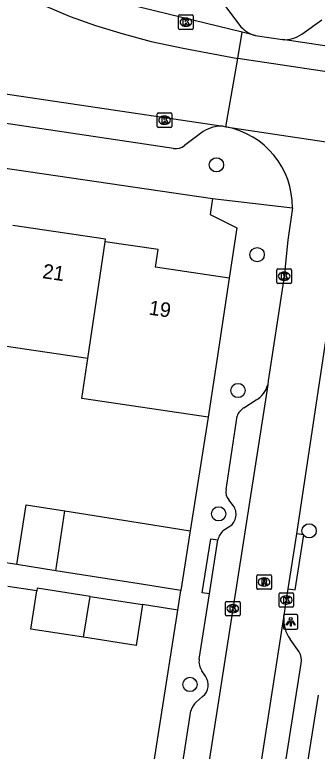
# Model space of a CAD drawing. Extents: x 163010 to 163853, y 382793 to 383982.
# Drawn here: x 163269.9 to 163290.6, y 383210.8 to 383261.3 of the extents above; entities that cross this region are included whole.
import ezdxf

# ---------------------------------------------------------------- set-up
doc = ezdxf.new("R2010")
doc.units = 0
for name, color, linetype in [('IMGEO_Boom', 7, 'Continuous'), ('IMGEO_Kolk', 7, 'Continuous'), ('IMGEO_Lichtpunt', 7, 'Continuous'), ('IMGEO_Muur', 7, 'Continuous'), ('IMGEO_Pand', 7, 'Continuous'), ('IMGEO_Pand_nummerreeks', 7, 'Continuous'), ('IMGEO_Rijbaan_lokaal_gesloten', 7, 'Continuous'), ('IMGEO_Rijbaan_lokaal_open', 7, 'Continuous'), ('IMGEO_Rioolput', 7, 'Continuous'), ('IMGEO_Voetpad_open', 7, 'Continuous')]:
    doc.layers.add(name, color=color, linetype=linetype)

msp = doc.modelspace()

# ---------------------------------------------------------------- linework, layer by layer
at = {"layer": 'IMGEO_Boom'}
for centre in [(163283.714, 383251.013), (163286.5, 383244.851), (163285.192, 383235.53), (163283.866, 383227.066), (163290.064, 383225.904), (163281.894, 383215.363)]:
    msp.add_circle(centre, 0.489, dxfattribs=at)
at = {"layer": 'IMGEO_Kolk'}
for p, q in [((163281.122, 383260.374), (163281.122, 383261.226)), ((163281.197, 383261.3), (163282.049, 383261.3)), ((163281.61, 383261.08), (163281.635, 383261.08)), ((163282.123, 383261.226), (163282.123, 383260.374)), ((163281.633, 383260.52), (163281.608, 383260.52)), ((163282.049, 383260.3), (163281.197, 383260.3)), ((163279.661, 383253.651), (163279.661, 383254.503)), ((163279.736, 383254.577), (163280.588, 383254.577)), ((163280.149, 383254.357), (163280.174, 383254.357)), ((163280.662, 383254.503), (163280.662, 383253.651)), ((163280.588, 383253.577), (163279.736, 383253.577)), ((163280.172, 383253.797), (163280.147, 383253.797)), ((163287.853, 383242.946), (163287.853, 383243.798)), ((163287.928, 383243.872), (163288.78, 383243.872)), ((163288.854, 383243.798), (163288.854, 383242.946)), ((163288.341, 383243.652), (163288.366, 383243.652)), ((163288.78, 383242.872), (163287.928, 383242.872)), ((163288.364, 383243.092), (163288.339, 383243.092)), ((163288, 383220.732), (163288, 383221.584)), ((163288.075, 383221.658), (163288.927, 383221.658)), ((163289.001, 383221.584), (163289.001, 383220.732)), ((163284.333, 383220.138), (163284.333, 383220.99)), ((163284.408, 383221.064), (163285.26, 383221.064)), ((163285.334, 383220.99), (163285.334, 383220.138)), ((163288.488, 383221.438), (163288.513, 383221.438)), ((163284.821, 383220.844), (163284.846, 383220.844)), ((163288.927, 383220.658), (163288.075, 383220.658)), ((163288.511, 383220.878), (163288.486, 383220.878)), ((163285.26, 383220.064), (163284.408, 383220.064)), ((163284.844, 383220.284), (163284.819, 383220.284))]:
    msp.add_line(p, q, dxfattribs=at)
for points in [[(163281.122, 383260.374), (163281.122, 383261.226)], [(163281.197, 383261.3), (163282.049, 383261.3)], [(163281.443, 383261), (163281.566, 383261), (163281.566, 383260.849), (163281.696, 383261), (163281.86, 383261), (163281.714, 383260.849), (163281.867, 383260.6), (163281.715, 383260.6), (163281.63, 383260.764), (163281.566, 383260.697), (163281.566, 383260.6), (163281.443, 383260.6), (163281.443, 383261)], [(163282.123, 383261.226), (163282.123, 383260.374)], [(163282.049, 383260.3), (163281.197, 383260.3)], [(163279.661, 383253.651), (163279.661, 383254.503)], [(163279.736, 383254.577), (163280.588, 383254.577)], [(163280.662, 383254.503), (163280.662, 383253.651)], [(163279.982, 383254.277), (163280.105, 383254.277), (163280.105, 383254.126), (163280.235, 383254.277), (163280.399, 383254.277), (163280.253, 383254.126), (163280.406, 383253.877), (163280.254, 383253.877), (163280.169, 383254.041), (163280.105, 383253.974), (163280.105, 383253.877), (163279.982, 383253.877), (163279.982, 383254.277)], [(163280.588, 383253.577), (163279.736, 383253.577)], [(163287.853, 383242.946), (163287.853, 383243.798)], [(163287.928, 383243.872), (163288.78, 383243.872)], [(163288.854, 383243.798), (163288.854, 383242.946)], [(163288.174, 383243.572), (163288.297, 383243.572), (163288.297, 383243.421), (163288.427, 383243.572), (163288.591, 383243.572), (163288.445, 383243.421), (163288.598, 383243.172), (163288.446, 383243.172), (163288.361, 383243.336), (163288.297, 383243.269), (163288.297, 383243.172), (163288.174, 383243.172), (163288.174, 383243.572)], [(163288.78, 383242.872), (163287.928, 383242.872)], [(163288, 383220.732), (163288, 383221.584)], [(163288.075, 383221.658), (163288.927, 383221.658)], [(163289.001, 383221.584), (163289.001, 383220.732)], [(163284.333, 383220.138), (163284.333, 383220.99)], [(163284.408, 383221.064), (163285.26, 383221.064)], [(163285.334, 383220.99), (163285.334, 383220.138)], [(163288.321, 383221.358), (163288.444, 383221.358), (163288.444, 383221.207), (163288.574, 383221.358), (163288.738, 383221.358), (163288.592, 383221.207), (163288.745, 383220.958), (163288.593, 383220.958), (163288.508, 383221.122), (163288.444, 383221.055), (163288.444, 383220.958), (163288.321, 383220.958), (163288.321, 383221.358)], [(163284.654, 383220.764), (163284.777, 383220.764), (163284.777, 383220.613), (163284.907, 383220.764), (163285.071, 383220.764), (163284.925, 383220.613), (163285.078, 383220.364), (163284.926, 383220.364), (163284.841, 383220.528), (163284.777, 383220.461), (163284.777, 383220.364), (163284.654, 383220.364), (163284.654, 383220.764)], [(163288.927, 383220.658), (163288.075, 383220.658)], [(163285.26, 383220.064), (163284.408, 383220.064)]]:
    msp.add_lwpolyline(points, dxfattribs=at)
for centre, start, end in [((163281.199, 383261.224), 91.552, 178.448), ((163281.199, 383261.224), 91.552, 178.448), ((163282.047, 383261.224), 1.552, 88.448), ((163282.047, 383261.224), 1.552, 88.448), ((163281.199, 383260.376), 181.552, 268.448), ((163281.199, 383260.376), 181.552, 268.448), ((163282.047, 383260.376), 271.552, 358.448), ((163282.047, 383260.376), 271.552, 358.448), ((163279.738, 383254.501), 91.552, 178.448), ((163279.738, 383254.501), 91.552, 178.448), ((163280.586, 383254.501), 1.552, 88.448), ((163280.586, 383254.501), 1.552, 88.448), ((163279.738, 383253.653), 181.552, 268.448), ((163279.738, 383253.653), 181.552, 268.448), ((163280.586, 383253.653), 271.552, 358.448), ((163280.586, 383253.653), 271.552, 358.448), ((163287.93, 383243.796), 91.552, 178.448), ((163287.93, 383243.796), 91.552, 178.448), ((163288.778, 383243.796), 1.552, 88.448), ((163288.778, 383243.796), 1.552, 88.448), ((163287.93, 383242.948), 181.552, 268.448), ((163287.93, 383242.948), 181.552, 268.448), ((163288.778, 383242.948), 271.552, 358.448), ((163288.778, 383242.948), 271.552, 358.448), ((163288.077, 383221.582), 91.552, 178.448), ((163288.077, 383221.582), 91.552, 178.448), ((163288.925, 383221.582), 1.552, 88.448), ((163288.925, 383221.582), 1.552, 88.448), ((163284.41, 383220.988), 91.552, 178.448), ((163284.41, 383220.988), 91.552, 178.448), ((163285.258, 383220.988), 1.552, 88.448), ((163285.258, 383220.988), 1.552, 88.448), ((163288.077, 383220.734), 181.552, 268.448), ((163288.077, 383220.734), 181.552, 268.448), ((163288.925, 383220.734), 271.552, 358.448), ((163288.925, 383220.734), 271.552, 358.448), ((163284.41, 383220.14), 181.552, 268.448), ((163284.41, 383220.14), 181.552, 268.448), ((163285.258, 383220.14), 271.552, 358.448), ((163285.258, 383220.14), 271.552, 358.448)]:
    msp.add_arc(centre, 0.0765, start, end, dxfattribs=at)
for centre, major_axis, ratio, start_param, end_param in [((163281.609, 383260.8), (-0.387, 0.002), 0.722429, 4.712389, 7.853982), ((163281.634, 383260.8), (-0.39, 0.002), 0.717154, 1.570796, 4.712389), ((163280.148, 383254.077), (-0.387, 0.002), 0.722429, 4.712389, 7.853982), ((163280.173, 383254.077), (-0.39, 0.002), 0.717154, 1.570796, 4.712389), ((163288.34, 383243.372), (-0.387, 0.002), 0.722429, 4.712389, 7.853982), ((163288.365, 383243.372), (-0.39, 0.002), 0.717154, 1.570796, 4.712389), ((163288.487, 383221.158), (-0.387, 0.002), 0.722429, 4.712389, 7.853982), ((163288.512, 383221.158), (-0.39, 0.002), 0.717154, 1.570796, 4.712389), ((163284.82, 383220.564), (-0.387, 0.002), 0.722429, 4.712389, 7.853982), ((163284.845, 383220.564), (-0.39, 0.002), 0.717154, 1.570796, 4.712389)]:
    msp.add_ellipse(centre, major_axis=major_axis, ratio=ratio, start_param=start_param, end_param=end_param, dxfattribs=at)
at = {"layer": 'IMGEO_Lichtpunt'}
for p, q in [((163288.305, 383220.057), (163288.305, 383219.25)), ((163288.305, 383220.057), (163288.305, 383219.25)), ((163289.207, 383220.152), (163288.399, 383220.152)), ((163289.207, 383220.152), (163288.399, 383220.152)), ((163289.301, 383219.25), (163289.301, 383220.057)), ((163289.301, 383219.25), (163289.301, 383220.057)), ((163288.399, 383219.156), (163289.207, 383219.156)), ((163288.399, 383219.156), (163289.207, 383219.156))]:
    msp.add_line(p, q, dxfattribs=at)
for points in [[(163288.679, 383219.721), (163288.718, 383219.693), (163288.53, 383219.431), (163288.492, 383219.458), (163288.679, 383219.721)], [(163288.781, 383219.673), (163288.828, 383219.673), (163288.828, 383219.351), (163288.781, 383219.351), (163288.781, 383219.673)], [(163288.891, 383219.693), (163288.929, 383219.72), (163289.116, 383219.458), (163289.077, 383219.43), (163288.891, 383219.693)]]:
    msp.add_lwpolyline(points, dxfattribs=at)
msp.add_circle((163288.804, 383219.855), 0.0994, dxfattribs=at)
for centre, start, end in [((163288.399, 383220.057), 90, 180), ((163288.399, 383220.057), 90, 180), ((163289.207, 383220.057), 0, 90), ((163289.207, 383220.057), 0, 90), ((163288.399, 383219.25), 180, 270), ((163288.399, 383219.25), 180, 270), ((163289.207, 383219.25), 270, 0), ((163289.207, 383219.25), 270, 360)]:
    msp.add_arc(centre, 0.0946, start, end, dxfattribs=at)
at = {"layer": 'IMGEO_Muur'}
for points in [[(163283.138, 383233.704), (163281.914, 383225.899)], [(163278.636, 383205.006), (163281.061, 383220.467)]]:
    msp.add_lwpolyline(points, dxfattribs=at)
at = {"layer": 'IMGEO_Pand'}
for points in [[(163276.084, 383245.735), (163276.111, 383245.918), (163269.752, 383246.858)], [(163274.893, 383237.731), (163276.084, 383245.735)], [(163284.577, 383243.244), (163279.531, 383243.986), (163279.71, 383245.203), (163276.084, 383245.735)], [(163284.577, 383243.244), (163283.726, 383237.452), (163283.138, 383233.704)], [(163274.893, 383237.731), (163268.532, 383238.666)], [(163283.138, 383233.704), (163274.489, 383234.972), (163274.893, 383237.731)], [(163270.026, 383223.597), (163270.68, 383227.696), (163273.326, 383227.273)], [(163272.713, 383223.168), (163273.326, 383227.273)], [(163273.326, 383227.273), (163279.359, 383226.308), (163281.914, 383225.899)], [(163281.914, 383225.899), (163281.271, 383221.8)], [(163272.713, 383223.168), (163270.026, 383223.597)], [(163281.271, 383221.8), (163278.703, 383222.21), (163272.713, 383223.168)], [(163274.603, 383218.6), (163270.991, 383219.164), (163271.399, 383221.78)], [(163275.052, 383221.405), (163271.429, 383221.97), (163271.399, 383221.78)], [(163274.603, 383218.6), (163275.052, 383221.405)], [(163275.052, 383221.405), (163278.651, 383220.843)], [(163278.651, 383220.843), (163278.213, 383218.037), (163274.603, 383218.6)]]:
    msp.add_lwpolyline(points, dxfattribs=at)
at = {"layer": 'IMGEO_Rijbaan_lokaal_gesloten'}
for points in [[(163259.805, 383267.54), (163261.871, 383267.087), (163264.002, 383266.241), (163265.531, 383265.482), (163268.17, 383263.899), (163269.993, 383262.898), (163271.849, 383261.958), (163273.697, 383261.198), (163275.426, 383260.58), (163277.327, 383260.004), (163279.243, 383259.481), (163281.431, 383259.01), (163285.184, 383258.317)], [(163285.467, 383260.115), (163275.24, 383262.639)], [(163285.184, 383258.317), (163285.467, 383260.115)], [(163286.363, 383259.893), (163285.467, 383260.115)], [(163286.363, 383259.893), (163288.229, 383259.608)], [(163242.921, 383259.802), (163284.168, 383253.665)], [(163352.608, 383249.943), (163288.229, 383259.608)], [(163284.361, 383253.616), (163285.184, 383258.317)], [(163352.91, 383248.164), (163285.184, 383258.317)], [(163284.168, 383253.665), (163284.361, 383253.616)]]:
    msp.add_lwpolyline(points, dxfattribs=at)
at = {"layer": 'IMGEO_Rijbaan_lokaal_open'}
for points in [[(163284.361, 383253.616), (163296.886, 383251.754), (163297.016, 383251.731)], [(163288.916, 383248.053), (163288.604, 383245.855), (163288.351, 383243.343), (163287.268, 383236.188), (163287.225, 383235.912)], [(163289.218, 383225.695), (163292.347, 383246.561), (163292.509, 383247.462)], [(163287.225, 383235.912), (163280.814, 383194.763)], [(163288.621, 383221.928), (163289.218, 383225.695)], [(163288.335, 383219.963), (163288.503, 383221.183), (163288.621, 383221.928)], [(163284.332, 383194.201), (163288.335, 383219.963)]]:
    msp.add_lwpolyline(points, dxfattribs=at)
msp.add_arc((163283.337, 383248.131), 5.58, 359.1973, 79.4242, dxfattribs=at)
at = {"layer": 'IMGEO_Rioolput'}
for p, q in [((163286.476, 383221.963), (163286.476, 383222.815)), ((163286.551, 383222.889), (163287.403, 383222.889)), ((163286.964, 383222.669), (163286.989, 383222.669)), ((163287.477, 383222.815), (163287.477, 383221.963)), ((163286.987, 383222.109), (163286.962, 383222.109)), ((163287.403, 383221.889), (163286.551, 383221.889))]:
    msp.add_line(p, q, dxfattribs=at)
for points in [[(163286.476, 383221.963), (163286.476, 383222.815)], [(163286.551, 383222.889), (163287.403, 383222.889)], [(163287.065, 383222.587), (163286.813, 383222.589), (163286.813, 383222.189)], [(163286.991, 383222.508), (163286.937, 383222.508), (163286.937, 383222.427)], [(163287.477, 383222.815), (163287.477, 383221.963)], [(163286.813, 383222.189), (163286.937, 383222.189), (163286.937, 383222.351), (163286.948, 383222.351)], [(163286.937, 383222.427), (163286.989, 383222.427)], [(163286.995, 383222.322), (163287.066, 383222.189), (163287.206, 383222.189), (163287.141, 383222.315)], [(163287.403, 383221.889), (163286.551, 383221.889)]]:
    msp.add_lwpolyline(points, dxfattribs=at)
for centre, radius, start, end in [((163286.553, 383222.813), 0.0765, 91.552, 178.448), ((163286.553, 383222.813), 0.0765, 91.552, 178.448), ((163286.997, 383222.412), 0.0964, 77.0061, 93.1865), ((163287.011, 383222.469), 0.0378, 276.6634, 79.6772), ((163287.064, 383222.477), 0.109, 350.3612, 89.416), ((163287.401, 383222.813), 0.0765, 1.552, 88.448), ((163287.401, 383222.813), 0.0765, 1.552, 88.448), ((163286.947, 383222.298), 0.0533, 26.0293, 88.6989), ((163286.973, 383222.616), 0.19, 274.7715, 282.9687), ((163287.062, 383222.477), 0.112, 277.5842, 350.9817), ((163287.046, 383222.262), 0.108, 29.5134, 73.7905), ((163286.553, 383221.965), 0.0765, 181.552, 268.448), ((163286.553, 383221.965), 0.0765, 181.552, 268.448), ((163287.401, 383221.965), 0.0765, 271.552, 358.448), ((163287.401, 383221.965), 0.0765, 271.552, 358.448)]:
    msp.add_arc(centre, radius, start, end, dxfattribs=at)
for centre, major_axis, ratio, start_param, end_param in [((163286.963, 383222.389), (-0.387, 0.002), 0.722429, 4.712389, 7.853982), ((163286.988, 383222.389), (-0.39, 0.002), 0.717154, 1.570796, 4.712389)]:
    msp.add_ellipse(centre, major_axis=major_axis, ratio=ratio, start_param=start_param, end_param=end_param, dxfattribs=at)
at = {"layer": 'IMGEO_Voetpad_open'}
for points in [[(163284.298, 383261.946), (163285.284, 383260.601)], [(163289.554, 383259.974), (163290.942, 383260.961)], [(163280.771, 383252.14), (163242.497, 383257.863), (163241.993, 383258.11), (163241.162, 383258.913)], [(163233.785, 383252.175), (163234.265, 383256.049), (163240.046, 383255.072), (163274.56, 383250), (163283.447, 383248.694)], [(163282.807, 383253.291), (163281.534, 383252.332)], [(163283.447, 383248.694), (163283.291, 383247.605), (163285.113, 383246.694), (163284.577, 383243.244)], [(163283.447, 383248.694), (163288.916, 383248.053)], [(163285.59, 383234.346), (163286.437, 383234.881)], [(163283.138, 383233.704), (163281.914, 383225.899)], [(163284.381, 383228.732), (163285.125, 383233.778)], [(163284.868, 383227.642), (163284.562, 383228.031)], [(163284.193, 383225.94), (163284.63, 383226.215)], [(163288.621, 383221.928), (163289.114, 383221.85), (163289.711, 383225.617), (163289.218, 383225.695)], [(163283.235, 383221.578), (163282.742, 383221.655), (163283.323, 383225.355), (163283.816, 383225.278)], [(163283.235, 383221.578), (163283.816, 383225.278)], [(163270.026, 383223.597), (163266.367, 383224.146)], [(163271.399, 383221.78), (163269.408, 383222.091)], [(163281.06, 383220.463), (163281.061, 383220.467), (163281.271, 383221.8)], [(163282.532, 383217.097), (163283.235, 383221.578)], [(163278.636, 383205.006), (163281.06, 383220.463)], [(163281.06, 383220.463), (163278.651, 383220.843)], [(163289.384, 383217.609), (163288.759, 383218.466)], [(163284.553, 383185.114), (163285.858, 383193.546), (163289.525, 383216.807)], [(163282.951, 383215.925), (163282.716, 383216.294)], [(163282.343, 383214.178), (163282.766, 383214.535)], [(163290.673, 383214.627), (163285.645, 383182.923)], [(163280.729, 383205.581), (163281.964, 383213.55)]]:
    msp.add_lwpolyline(points, dxfattribs=at)
for centre, radius, start, end in [((163286.93, 383261.934), 2.118, 218.9925, 254.4647), ((163288.39, 383261.607), 2.006, 265.403, 305.4801), ((163284.034, 383251.488), 2.181, 86.4904, 124.2406), ((163280.892, 383253.271), 1.137, 263.8848, 304.3643), ((163285.654, 383236.296), 1.617, 298.9485, 346.2697), ((163286.224, 383233.353), 1.178, 122.538, 158.8502), ((163285.174, 383228.563), 0.811, 167.9727, 220.9827), ((163284.044, 383227.046), 1.017, 305.199, 35.8633), ((163285.062, 383225.007), 1.275, 132.9548, 167.7233), ((163290.618, 383219.801), 2.289, 175.9441, 215.6837), ((163288.085, 383216.967), 1.449, 353.6563, 26.2863), ((163283.579, 383216.914), 1.063, 170.0977, 215.7143), ((163282.145, 383215.325), 1.005, 308.1704, 36.6673), ((163283.164, 383213.254), 1.236, 131.632, 166.1458)]:
    msp.add_arc(centre, radius, start, end, dxfattribs=at)

# ---------------------------------------------------------------- texts
at = {"layer": 'IMGEO_Pand_nummerreeks'}
for s, rotation, p in [('21', 351.589, (163271.746, 383243.247)), ('19', 351.636, (163279.036, 383240.743))]:
    msp.add_text(s, height=1, rotation=rotation, dxfattribs=at).set_placement(p)

doc.saveas('drawing.dxf')
